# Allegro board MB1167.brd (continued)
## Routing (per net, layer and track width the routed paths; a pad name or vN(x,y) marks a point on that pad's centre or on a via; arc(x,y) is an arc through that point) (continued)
VBUS_FS1: length 209.4
  TOP w0.203: v1(9.27,101.47) 9.27,100.71 8.68,100.12 D5.B3
  TOP w0.381: v1(6.73,97.03) 5.36,98.4 CN13.1
  TOP w0.508: v1(111.89,124.26) 112.88,124.26 114.2,122.94 CN6.54 ; v1(6.73,97.03) 6.73,97 7.24,96.49 C48.1 8.31,93.29 U11.1 ; v1(9.27,101.47) 10.16,102.36 10.16,102.87 v1(10.67,103.38) R108.1 ; D9.1 v1(25.91,81.03)
  L4_SIG w0.508: v1(10.67,103.38) 11.05,103.76 19.68,103.76 22.35,101.09 24.64,101.09 26.42,99.31 32.79,99.31 36.96,103.48 36.96,105.41 43.69,112.14 43.69,116.33 46.37,119.01 46.44,119.01 48.59,121.16 58.8,121.16 60.69,119.27 95.52,119.27 97.66,121.41 106.43,121.41 108.97,123.95 108.97,126.11 107.95,127.13 107.95,127.89 v1(108.08,128.02) 110.62,128.02 111.89,126.75 v1(111.89,124.26) ; JP13.3 3.18,74.17 3.18,76.35 5.16,78.33 5.16,81.48 6.1,82.42 6.1,94.74 6.73,95.38 v1(6.73,97.03) 6.73,97.69 6.02,98.4 6.02,100.51 6.99,101.47 v1(9.27,101.47)
  BOTTOM w0.508: JP13.3 5.84,71.5 8.94,71.5 9.4,71.96 21.03,71.96 25.91,76.83 v1(25.91,81.03) ; v1(108.08,128.02) R261.2
VBUS_FS2: length 124.4
  TOP w0.254: v1(9.83,87.76) 9.83,86.79 8.81,85.77 D6.B3
  TOP w0.381: 5.36,84.04 CN14.1
  TOP w0.508: 5.36,84.04 5.87,84.04 7.37,82.55 R138.1 7.24,81.15 v1(6.1,81.15) ; SB13.1 v1(15.88,114.05) ; v1(39.37,129.29) 38.73,128.65 38.73,126.24 36.83,124.33 v1(29.84,124.33) ; D10.1 26.82,78.05 v1(26.75,77.98)
  L4_SIG w0.508: v1(6.1,81.15) 7.24,82.3 7.24,83.95 8,84.71 8,85.09 9.83,86.92 v1(9.83,87.76)
  BOTTOM w0.508: v1(6.1,81.15) 2.67,77.72 2.67,72.14 JP13.5 5.72,69.09 8.76,69.09 10.24,70.56 20.88,70.56 26.75,76.43 v1(26.75,77.98) ; v1(9.83,87.76) 9.91,87.83 9.91,106.81 10.67,107.57 11.81,107.57 14.73,110.49 14.73,112.9 v1(15.88,114.05) 15.88,116.89 17.48,118.49 20.95,118.49 23.62,121.16 23.62,122.68 25.27,124.33 v1(29.84,124.33) ; v1(39.37,129.29) R259.1
VBUS_HS: length 77.2
  TOP w0.203: v1(7.37,115.75) 7.75,116.13 D3.A1
  TOP w0.381: CN8.1 6.96,111.86 L2.2
  TOP w0.508: L2.2 v1(7.37,113.18) ; D8.1 v1(25.53,83.06)
  BOTTOM w0.508: v1(25.53,83.06) 25.4,83.06 25.15,82.8 25.15,77.34 21.84,74.04 5.84,74.04 JP13.1 4.57,77.98 7.16,80.56 7.16,82.63 5.97,83.82 5.97,100.58 7.37,101.98 v1(7.37,113.18) v1(7.37,115.75)
VDD_MCU: length 47.4
  TOP w0.381: U4.F5 v5(80.41,140.09) ; U4.E9 v5(81.21,136.89) U4.E8 ; v5(79.61,134.49) U4.G11 ; U4.F4 v5(80.41,140.89) ; v5(81.21,135.29) U4.E10 ; U4.K11 v5(76.41,134.49) ; v5(79.61,140.09) U4.G5 ; U4.F11 v5(80.41,134.49) ; U4.L8 v5(76.41,136.89) ; U4.E7 v5(80.41,138.49) ; U4.J5 v5(77.22,139.29) ; U4.H5 v5(78.01,139.29) ; U4.J11 v5(77.21,134.49) ; U4.H11 v5(78.01,134.49) ; U4.K5 v5(76.41,140.09) ; v5(75.61,138.49) U4.L7 ; U4.L10 v5(75.61,135.29) ; U4.L9 v5(75.61,136.09)
  TOP w0.508: C28.2 60.33,130.81 v1(60.2,130.68) ; C26.2 89.1,133.86 v1(88.77,134.19)
  BOTTOM w0.381: C122.1 81.92,137.59 v5(81.21,136.89) ; v5(75.61,138.49) 75.31,138.19 C125.1 ; v5(81.28,143.38) 81.66,143.76 C108.1 ; v5(78.01,139.29) 78.17,139.45 C118.1 ; C129.1 75.79,136.27 v5(75.61,136.09) ; v3(85.95,138.29) 85.83,138.18 85.72,138.18 85.34,137.79 C121.1 ; C132.1 72.64,135.38 72.14,134.87 v5(72.01,134.87) ; v3(77.93,145.01) 77.93,144.88 77.9,144.86 77.9,144.58 78.02,144.47 78.02,144.23 C109.1 ; v1(86.94,149.56) 86.49,149.1 C104.2 ; C131.1 78.74,135.36 v5(79.61,134.49) ; v5(85.72,140.84) 85.43,140.54 85.05,140.54 C116.1 ; C126.1 72.64,137.8 v5(72.06,138.38) 72.62,138.94 C117.1 ; C130.1 85.27,136.14 85.67,135.74 86.2,135.74 v5(86.28,135.66) ; C128.1 80.77,135.73 v5(81.21,135.29) ; v5(78.01,134.49) 78.26,134.24 C133.1 ; C123.1 80.77,138.12 v5(80.41,138.49) ; v5(79.61,140.09) 79.11,140.59 C114.1 ; v5(76.41,136.89) 76.45,136.93 C124.1
  BOTTOM w0.508: JP2.2 61.09,150.57 ; JP2.2 62.05,149.61 ; JP2.2 60.12,149.61 ; JP2.2 61.09,148.64 ; 61.09,146.3 61.09,147.27 ; 61.09,146.3 61.09,145.34 ; 61.09,146.3 60.25,146.3 ; 61.09,146.3 61.93,146.3 ; 61.09,142.67 61.09,143.64 ; 61.09,143.64 60.25,143.64 ; 61.09,143.64 61.93,143.64 ; 61.09,143.64 61.09,144.6 ; C115.1 59.94,141.58 ; C115.1 59.94,140.61 ; C115.1 60.43,141.1 ; 61.2,141.1 L7.1 ; L7.1 61.85,140.49 ; L7.1 61.85,141.71 ; C127.2 v1(59.94,137.41)
  vias: v1(60.2,139.95) v1(60.2,139.32) v1(60.96,139.95) v1(60.96,139.32) v1(61.72,139.95) v1(61.72,139.32)
VDDA: length 15.6
  TOP w0.381: U4.R1 72.26,142.89 72.14,143.01 v5(72.14,143.05)
  TOP w0.508: v3(68.07,143.64) 67.06,143.64 R33.1
  BOTTOM w0.381: C113.2 72.52,142.67 v5(72.14,143.05)
  BOTTOM w0.508: L7.2 TP9.1 C111.1 v3(68.07,143.64) 68.71,143.64 69.29,143.05 v5(72.14,143.05)
A0: length 133.9
  TOP w0.102: U13.G8 91.83,76.34 v5(91.44,75.95) ; 78.84,107.95 77.47,106.58 77.47,105.81 U9.E2 ; v5(69.74,77.85) 69.74,78.09 69.22,78.61 U14.A3
  TOP w0.127: 78.84,107.95 78.84,108.03 v4(78.89,108.08) ; CN11.14 v3(103.38,109.78)
  L4_SIG w0.102: v5(69.74,77.85) 69.74,77.84 70.21,77.37 71.32,77.37 71.42,77.47 71.7,77.47 71.9,77.27 72.11,77.27 72.31,77.47 72.51,77.47 72.72,77.27 72.92,77.27 73.12,77.47 73.33,77.47 73.53,77.27 73.73,77.27 73.94,77.47 74.14,77.47 74.34,77.27 74.55,77.27 74.75,77.47 74.95,77.47 75.16,77.27 75.36,77.27 75.56,77.47 75.77,77.47 75.97,77.27 76.17,77.27 76.38,77.47 76.58,77.47 76.78,77.27 76.98,77.27 77.19,77.47 77.39,77.47 77.59,77.27 77.8,77.27 78,77.47 78.2,77.47 78.41,77.27 78.61,77.27 78.81,77.47 79.21,77.47 v1(79.29,77.39) 79.57,77.11 83.59,77.11 84.28,77.81 89.83,77.81 91.44,76.2 v5(91.44,75.95) ; v3(103.38,109.78) 102.9,109.3 101.35,109.3 98.48,106.43 80.17,106.43 78.89,107.71 v4(78.89,108.08)
  BOTTOM w0.127: v1(79.29,77.39) 79.29,78.5 79.5,78.71 79.5,79.6 80.53,80.63 80.53,94.39 80.8,94.65 80.8,97.64 82.8,99.64 82.8,99.69 82.82,99.7 82.82,100.06 81.92,100.97 80.52,100.97 79.88,101.6 79.88,104.14 78.89,105.13 v4(78.89,108.08) ; R242.2 91.02,142.24 91.52,141.74 91.53,141.74 93.98,139.29 93.98,132.59 93.34,131.95 93.34,117.6 101.73,109.22 102.82,109.22 v3(103.38,109.78)
A1: length 133.4
  TOP w0.102: 79.88,107.95 78.51,106.58 78.51,105.77 U9.D2 ; U14.A4 69.2,77.86 v5(69.2,77.85) ; U13.G9 91.44,75.12 v5(91.44,75.06)
  TOP w0.127: 79.88,107.95 79.93,108 79.93,108.31 v4(80.26,108.64) ; CN11.12 v3(103.38,111.05)
  L4_SIG w0.102: v4(80.26,108.64) 80.26,108.46 81.53,107.19 97.89,107.19 101.22,110.52 102.84,110.52 v3(103.38,111.05) ; v5(91.44,75.06) 91.01,75.48 91.01,76.09 89.6,77.5 84.49,77.5 83.77,76.78 80.49,76.78 v1(80.39,76.68) 80.29,76.68 80.26,76.71 79.5,76.71 79.25,76.96 69.96,76.96 69.2,77.72 v5(69.2,77.85)
  BOTTOM w0.127: v1(80.39,76.68) 80.39,77.34 81.41,78.36 81.41,79.35 82.36,80.3 82.36,82.71 82.98,83.33 82.98,86.49 85.09,88.6 85.09,102.11 83.03,104.17 83.03,105.66 80.26,108.43 v4(80.26,108.64) ; R240.2 91.44,142.75 92.04,142.75 93.22,141.57 93.22,141.13 94.74,139.61 94.74,132.21 94.11,131.57 94.11,118.19 101.83,110.46 102.9,110.46 103.38,110.95 v3(103.38,111.05)
A2: length 130.1
  TOP w0.102: v5(70.89,77.72) 70.87,77.72 70.25,77.11 U14.A5 ; 81.33,107.95 81.33,107.62 80.47,106.76 80.47,105.93 U9.C2 ; v5(91.44,77.72) 92.08,77.72 U13.F7
  TOP w0.127: v4(81.33,108.53) 81.33,107.95 ; CN11.8 v3(103.38,113.59)
  L4_SIG w0.102: v5(70.89,77.72) 70.97,77.72 71.07,77.82 79.66,77.82 79.93,77.55 v1(81.41,77.55) 83.49,77.55 84.06,78.11 84.45,78.11 84.46,78.11 91.06,78.11 v5(91.44,77.72) ; v4(81.33,108.53) 81.92,107.95 96.95,107.95 101.98,112.98 102.77,112.98 v3(103.38,113.59)
  BOTTOM w0.127: v3(103.38,113.59) 102.77,112.98 100.69,112.98 94.87,118.8 94.87,131.06 95.5,131.7 95.5,139.92 93.98,141.45 93.98,141.99 92.08,143.89 91.57,143.89 R239.2 ; v4(81.33,108.53) 81.33,108.51 83.92,105.92 83.92,104.36 85.85,102.43 85.85,88.24 83.74,86.13 83.74,82.98 83.44,82.68 83.44,80.14 83.12,79.82 82.42,79.82 81.79,79.19 81.79,77.98 81.41,77.6 v1(81.41,77.55)
A3: length 127.3
  TOP w0.102: U14.B3 v5(68.29,78.98) ; v5(92.2,79.88) U13.F3 ; U9.A2 81.94,105.37 82.45,105.88 82.45,107.95
  TOP w0.127: v4(82.25,108.66) 82.45,108.46 82.45,107.95 ; v3(101.98,114.68) 101.8,114.86 CN11.5
  L4_SIG w0.102: v3(101.98,114.68) 101.85,114.68 96.77,109.6 83.97,109.6 83.41,109.04 82.6,109.04 82.25,108.69 v4(82.25,108.66) ; v5(92.2,79.88) 93.22,79.88 93.34,80.01 93.34,80.21 93.22,80.34 91.9,80.34 91.77,80.21 91.77,79.78 91.67,79.68 91.52,79.68 91.41,79.78 91.41,80.31 91.31,80.42 91.16,80.42 91.06,80.31 91.06,79.81 90.93,79.68 83.24,79.68 v1(82.93,79.38) 82.61,79.69 70.32,79.69 69.75,79.12 68.43,79.12 v5(68.29,78.98)
  BOTTOM w0.127: v1(82.93,79.38) 83.69,79.38 83.95,79.63 83.95,82.55 84.12,82.73 84.12,85.95 86.23,88.06 86.23,102.59 84.23,104.59 84.23,106.37 82.25,108.35 v4(82.25,108.66) ; v3(101.98,114.68) 101.12,114.68 97.54,118.26 97.54,130.53 96.9,131.17 96.9,139.7 95,141.6 95,142.24 92.08,145.16 91.57,145.16 R236.2
A4: length 133.3
  TOP w0.102: 81.79,107.95 81.79,106.93 81.43,106.58 81.43,105.89 U9.B2 ; v5(92.24,81.53) 92.2,81.57 92.2,81.6 U13.G1 ; U14.B4 68.3,77.47 69.98,77.47 70.23,77.72 70.23,79.01 70.35,79.13 v5(70.35,79.17)
  TOP w0.127: v3(101.93,115.7) 101.6,115.7 101.17,116.13 CN11.3 ; 81.79,107.95 81.79,109.09 82.25,109.55 v4(82.25,109.58)
  L4_SIG w0.102: v5(70.35,79.17) 70.39,79.17 70.61,79.39 82.07,79.39 v1(82.36,79.1) 82.44,79.1 82.61,78.92 83.11,78.92 83.54,79.35 93.73,79.35 93.85,79.48 93.85,81.41 93.73,81.53 v5(92.24,81.53) ; v3(101.93,115.7) 101.6,115.7 96.39,110.49 83.49,110.49 82.58,109.58 v4(82.25,109.58)
  BOTTOM w0.127: R233.2 91.31,147.19 95.9,142.61 96.22,142.61 97.66,141.16 97.66,131.83 99.95,129.54 99.95,117.68 v3(101.93,115.7) ; v4(82.25,109.58) 82.68,109.14 82.68,108.46 82.96,108.18 85.17,105.97 85.17,104.19 86.74,102.62 86.74,88.01 84.51,85.78 84.51,82.57 84.33,82.39 84.33,79.43 83.64,78.74 82.72,78.74 v1(82.36,79.1)
A5: length 132
  TOP w0.102: 79.5,107.95 78.31,106.76 78.31,104.97 U9.D3 ; U13.G2 92.2,80.8 92.2,80.77 v5(92.22,80.75) ; U14.C3 v5(67.54,78.98)
  TOP w0.127: v4(80.39,109.4) 80.19,109.4 79.5,108.71 79.5,107.95 ; CN11.1 101.07,117.4 v3(101.85,118.19)
  L4_SIG w0.102: v4(80.39,109.4) 80.44,109.4 82.04,111 94.67,111 v3(101.85,118.19) ; v5(67.54,78.98) 68.01,79.45 69.75,79.45 70.31,80.01 82.65,80.01 v1(82.91,80.26) 84.18,80.26 84.56,79.88 90.65,79.88 90.78,80.01 90.78,80.14 90.65,80.26 90.37,80.26 90.25,80.39 90.25,80.52 90.37,80.64 90.7,80.64 90.83,80.77 90.83,81.03 90.95,81.15 91.13,81.15 91.26,81.03 91.26,80.82 91.36,80.72 91.56,80.72 91.66,80.82 91.66,81.05 91.76,81.15 93.38,81.15 93.5,81.03 93.5,80.87 93.38,80.75 v5(92.22,80.75)
  BOTTOM w0.127: v4(80.39,109.4) 80.87,108.92 80.87,108.36 81.28,107.95 83.54,105.69 83.54,104.2 85.47,102.27 85.47,88.42 83.36,86.31 83.36,83.17 82.91,82.72 v1(82.91,80.26) ; v3(101.85,118.19) 100.33,123.83 100.33,129.76 98.04,134.42 98.04,141.99 95.87,144.16 95.11,144.16 R232.2
A6: length 127.5
  TOP w0.102: U14.C4 v5(67.54,77.48) ; U9.C3 v4(80.41,104.87) ; v5(91.44,78.99) 91.44,79.6 91.64,79.8 91.64,80.12 U13.G3
  TOP w0.127: CN10.5 52.78,114.86 v3(53.47,114.17)
  L4_SIG w0.102: v5(67.54,77.48) 68.26,78.21 79.7,78.21 79.93,77.98 v1(80.33,77.98) 83.49,77.98 83.93,78.42 84.39,78.42 84.45,78.36 90.81,78.36 v5(91.44,78.99) ; v3(53.47,114.17) 53.98,114.17 54.48,113.67 69.72,113.67 78.52,104.87 v4(80.41,104.87)
  BOTTOM w0.127: R255.2 66.04,132.84 65.41,132.21 63.37,132.21 62.87,131.7 62.87,121.11 56.57,114.81 54.1,114.81 v3(53.47,114.17) ; v1(80.33,77.98) 80.33,79.35 81.6,80.62 81.6,83.25 82.22,83.87 82.22,91.08 82.35,91.21 84.2,91.21 84.33,91.34 84.33,91.59 84.2,91.72 82.35,91.72 82.22,91.85 82.22,92.1 82.35,92.23 84.2,92.23 84.33,92.35 84.33,92.61 84.2,92.74 82.35,92.74 82.22,92.86 82.22,93.12 82.35,93.24 84.2,93.24 84.33,93.37 84.33,101.88 83.95,102.26 83.95,102.49 83.31,103.12 82.17,103.12 81.74,103.55 81.74,103.73 81.8,103.79 81.8,103.97 81.62,104.15 81.44,104.15 81.38,104.09 81.2,104.09 80.42,104.87 v4(80.41,104.87)
A7: length 131.6
  TOP w0.102: U13.H1 91.44,81.56 91.44,79.88 90.68,79.12 90.45,79.12 v5(90.32,78.99) ; U14.D4 v5(66.79,77.48) ; U9.A3 v4(81.45,104.83)
  TOP w0.127: v3(53.47,115.44) 53.34,115.44 52.65,116.13 CN10.3
  L4_SIG w0.102: v3(53.47,115.44) 54.13,114.78 70.64,114.78 79.88,105.54 80.74,105.54 v4(81.45,104.83) ; v5(66.79,77.48) 67.72,78.41 69.49,78.41 69.6,78.51 80.84,78.51 v1(80.87,78.49) 81.07,78.28 83.36,78.28 83.82,78.74 84.45,78.74 84.56,78.64 90.27,78.64 90.32,78.69 v5(90.32,78.99)
  BOTTOM w0.127: v3(53.47,115.44) 54.34,115.44 54.69,115.8 56.34,115.8 62.08,121.54 62.08,132.44 63.12,133.48 65.15,133.48 65.79,134.11 R253.2 ; v1(80.87,78.49) 80.87,79.35 81.98,80.46 81.98,82.87 82.6,83.49 82.6,87.6 82.73,87.72 83.67,87.72 83.79,87.85 83.79,88.1 83.67,88.23 82.73,88.23 82.6,88.36 82.6,88.65 82.73,88.77 84.58,88.77 84.71,88.9 84.71,89.15 84.58,89.28 82.75,89.28 82.63,89.41 82.63,89.66 82.75,89.79 84.58,89.79 84.71,89.92 84.71,90.17 84.58,90.3 82.75,90.3 82.63,90.42 82.63,90.68 82.75,90.81 84.58,90.81 84.71,90.93 84.71,101.95 84.45,102.21 84.45,102.36 83.19,103.63 82.91,103.63 81.71,104.83 v4(81.45,104.83)
A8: length 135.3
  TOP w0.102: v4(81.41,101.88) 81.41,101.87 U9.B6 ; v5(90.66,81.54) U13.H2 ; U14.H2 v5(63.04,79.73)
  TOP w0.127: v3(54.9,115.3) 54.91,115.32 54.99,115.32 55.8,116.13 CN10.4
  L4_SIG w0.102: v5(63.04,79.73) 63.04,80.26 63.37,80.6 63.37,83.31 64.9,84.84 v1(81.37,84.84) 81.37,85.88 81.5,86 81.74,86 81.86,85.88 81.86,85.5 81.99,85.37 82.22,85.37 82.32,85.47 82.32,85.89 82.44,86 82.61,86 82.73,85.89 82.73,85.47 82.83,85.37 83.03,85.37 83.13,85.47 83.13,85.89 83.25,86 83.42,86 83.54,85.89 83.54,85.47 83.64,85.37 83.85,85.37 83.95,85.47 83.95,85.89 84.07,86 84.23,86 84.35,85.89 84.35,85.47 84.45,85.37 84.66,85.37 84.76,85.47 84.76,85.89 84.88,86 85.05,86 85.17,85.89 85.17,85.47 85.27,85.37 85.47,85.37 85.57,85.47 85.57,85.89 85.69,86 85.86,86 85.98,85.89 85.98,85.47 86.08,85.37 86.33,85.37 86.46,85.5 86.46,85.88 86.59,86 86.74,86 86.87,85.88 86.87,84.86 87,84.73 87.86,84.73 87.96,84.84 87.96,85.29 88.06,85.39 88.27,85.39 88.37,85.29 88.37,84.84 88.47,84.73 89.87,84.73 90.27,84.33 90.27,82.22 90.66,81.83 v5(90.66,81.54) ; v4(81.41,101.88) 81.92,102.39 81.92,104.92 81.1,105.74 80.11,105.74 70.55,115.3 v3(54.9,115.3)
  BOTTOM w0.127: v1(81.37,84.84) 81.37,94.09 81.56,94.28 81.56,95.96 81.69,96.09 83.44,96.09 83.57,96.22 83.57,96.47 83.44,96.6 81.84,96.6 81.71,96.72 81.71,96.98 81.84,97.1 83.44,97.1 83.57,97.23 83.57,97.49 83.44,97.61 82.42,97.61 82.3,97.74 82.3,97.99 82.42,98.12 83.44,98.12 83.57,98.25 83.57,100.2 82.18,101.59 82.18,102.02 81.33,102.87 80.85,102.87 80.72,103 80.72,103.45 80.59,103.58 80.34,103.58 80.21,103.45 80.21,102.46 80.34,102.34 81.28,102.34 81.41,102.21 v4(81.41,101.88) ; v3(54.9,115.3) 54.91,115.32 56.41,115.32 62.46,121.36 62.46,131.93 63.37,132.84 R256.2
A9: length 134.9
  TOP w0.102: U14.H3 v5(63.04,78.98) ; v4(83.31,101.21) 82.07,101.21 U9.A6 ; v5(89.86,80.74) U13.J3
  TOP w0.127: CN10.18 v3(54.86,107.24)
  L4_SIG w0.102: v5(89.86,80.74) 89.86,80.99 90.22,81.36 90.22,81.86 89.92,82.17 89.92,84.25 89.79,84.38 86.56,84.38 86.46,84.48 86.46,84.94 86.36,85.04 86.15,85.04 86.05,84.94 86.05,84.4 85.93,84.28 85.76,84.28 85.64,84.4 85.64,84.95 85.52,85.06 85.36,85.06 85.24,84.95 85.24,84.45 85.12,84.33 84.95,84.33 84.83,84.45 84.83,84.95 84.71,85.06 84.54,85.06 84.42,84.95 84.42,84.19 84.31,84.07 84.14,84.07 84.02,84.19 84.02,84.95 83.9,85.06 83.73,85.06 83.61,84.95 83.61,84.19 83.49,84.07 83.32,84.07 83.21,84.19 83.21,84.95 83.09,85.06 82.92,85.06 82.8,84.95 82.8,84.2 82.67,84.07 82.45,84.07 82.32,84.2 82.32,84.94 82.19,85.06 81.97,85.06 81.84,84.94 81.84,84.33 81.71,84.2 v1(81.37,84.2) 64.9,84.2 63.75,83.06 63.75,80.58 63.43,80.26 63.43,79.38 v5(63.04,78.98) ; v4(83.31,101.21) 82.54,101.21 82.17,100.84 79.54,100.84 78.9,101.48 76.54,101.48 76.51,101.51 73.04,101.51 72.69,101.85 71.78,101.85 71.25,101.32 70.84,101.32 64.92,107.24 v3(54.86,107.24)
  BOTTOM w0.127: R266.2 68.07,125.09 68.07,117.47 57.91,107.31 54.94,107.31 v3(54.86,107.24) ; v1(81.37,84.2) 81.37,84.21 81.84,84.68 81.84,93.52 81.97,93.65 83.82,93.65 83.95,93.78 83.95,94.03 83.82,94.16 82.07,94.16 81.94,94.28 81.94,94.54 82.07,94.67 83.82,94.67 83.95,94.79 83.95,95.05 83.82,95.17 82.07,95.17 81.94,95.3 81.94,95.55 82.07,95.68 83.82,95.68 83.95,95.81 83.95,101.73 83.82,101.85 82.98,101.85 82.85,101.73 82.85,101.33 82.98,101.21 v4(83.31,101.21)
A10: length 133.1
  TOP w0.102: v5(91.48,76.76) U13.G7 ; U9.C6 79.93,101.37 v4(80.41,101.85) ; U14.H4 v5(63.04,77.48)
  TOP w0.127: CN10.6 55.42,114.86 v3(54.74,114.17)
  L4_SIG w0.102: v3(54.74,114.17) 70.74,114.17 79.65,105.26 80.57,105.26 80.8,105.03 80.8,102.25 v4(80.41,101.85) ; v5(91.48,76.76) 91.8,76.45 91.8,74.85 90.18,73.24 89.32,73.24 88.75,72.67 88.58,72.67 88.09,73.16 87.94,73.16 87.8,73.02 87.8,72.87 88.38,72.29 88.38,72.13 88.26,72.01 88.09,72.01 87.51,72.59 87.37,72.59 87.23,72.44 87.23,72.3 87.76,71.77 87.76,71.67 87.34,71.25 v1(79.38,71.25) 67.23,71.25 62.61,75.87 62.61,77.05 v5(63.04,77.48)
  BOTTOM w0.127: v1(79.38,71.25) 79.88,71.75 79.88,79.44 80.91,80.47 80.91,94.22 81.18,94.49 81.18,97.43 83.19,99.44 83.19,100.15 81.99,101.35 80.92,101.35 v4(80.41,101.85) ; v3(54.74,114.17) 54.86,114.3 56.74,114.3 63.25,120.8 63.25,131.19 R258.2
A11: length 134.5
  TOP w0.102: U9.D6 78.36,101.92 v4(78.36,103.89) ; U14.H5 v5(63.04,76.73) ; v5(90.66,75.14) U13.H9
  TOP w0.127: CN10.7 52.91,113.59 v3(53.34,113.16)
  L4_SIG w0.102: v4(78.36,103.89) 78.36,104.52 71.25,111.63 62.68,111.63 62.57,111.73 62.57,111.91 62.47,112.01 62.27,112.01 62.17,111.91 62.17,111.73 62.07,111.63 61.86,111.63 61.76,111.73 61.76,111.91 61.66,112.01 61.46,112.01 61.36,111.91 61.36,111.73 61.25,111.63 61.05,111.63 60.95,111.73 60.95,111.91 60.85,112.01 60.64,112.01 60.54,111.91 60.54,111.73 60.44,111.63 60.24,111.63 60.14,111.73 60.14,111.91 60.03,112.01 59.83,112.01 59.73,111.91 59.73,111.73 59.63,111.63 59.43,111.63 59.32,111.73 59.32,111.91 59.22,112.01 59.02,112.01 58.92,111.91 58.92,111.73 58.82,111.63 58.61,111.63 58.51,111.73 58.51,111.91 58.41,112.01 58.21,112.01 58.1,111.91 58.1,111.73 58,111.63 57.8,111.63 57.7,111.73 57.7,111.91 57.6,112.01 57.39,112.01 57.29,111.91 57.29,111.73 57.19,111.63 56.99,111.63 56.89,111.73 56.89,111.91 56.78,112.01 56.58,112.01 56.48,111.91 56.48,111.73 56.38,111.63 56.17,111.63 56.07,111.73 56.07,111.91 55.97,112.01 55.77,112.01 55.67,111.91 55.67,111.73 55.56,111.63 54.48,111.63 53.98,112.14 53.98,112.52 v3(53.34,113.16) ; v5(90.66,75.14) 90.66,74.17 90.18,73.7 89.15,73.7 89.05,73.8 89.05,74.68 88.93,74.8 88.77,74.8 88.65,74.68 88.65,73.8 88.54,73.7 88.02,73.7 86.71,72.38 86.71,72.24 86.93,72.02 86.93,71.87 86.79,71.73 86.65,71.73 86.42,71.95 86.28,71.95 86.08,71.75 v1(78.61,71.75) 67.31,71.75 63.4,75.67 63.4,76.38 v5(63.04,76.73)
  BOTTOM w0.127: v1(78.61,71.75) 79.5,72.64 79.5,76.55 78.49,77.57 78.49,79.66 79.76,80.93 79.76,94.82 80.01,95.07 80.01,98.68 78.99,99.69 78.99,100.84 78.87,100.97 78.87,103.38 v4(78.36,103.89) ; v3(53.34,113.16) 53.85,113.67 56.69,113.67 63.65,120.62 63.65,128.93 R257.2
A12: length 116.3
  TOP w0.102: v5(63.79,78.98) U14.G3 ; U9.B7 v4(81.41,99.87)
  TOP w0.127: CN10.33 53.29,97.08 v3(53.42,97.21)
  L4_SIG w0.102: v4(81.41,99.87) 81.41,99.87 81.41,98.68 79.78,97.05 75.41,97.05 75.08,97.38 55.68,97.38 55.02,96.72 54.28,96.72 53.8,97.21 v3(53.42,97.21)
  BOTTOM w0.127: v5(63.79,78.98) 64.77,79.96 68.72,79.96 69.11,80.35 69.11,82.22 66.42,84.91 66.42,100.33 70.99,104.9 74.68,104.9 74.93,105.16 78.52,105.16 79.63,104.05 79.63,101.47 81.23,99.87 v4(81.41,99.87) ; v3(53.42,97.21) 54,97.79 56.26,97.79 73.66,115.19 73.66,122.17 R272.2
A13: length 120.6
  TOP w0.102: v5(63.79,77.48) U14.G4 ; U9.A7 v4(82.41,99.87)
  TOP w0.127: v3(54.86,97.28) 55.07,97.08 CN10.34
  L4_SIG w0.102: v3(54.86,97.28) 55.02,97.28 55.45,97.71 75.26,97.71 75.59,97.38 79.48,97.38 80.9,98.81 80.9,99.92 81.31,100.33 81.95,100.33 v4(82.41,99.87)
  BOTTOM w0.127: R262.2 74.68,125.09 74.68,123.96 74.42,123.7 74.42,121.79 74.04,121.41 74.04,114.81 56.44,97.21 54.94,97.21 v3(54.86,97.28) ; v5(63.79,77.48) 64.29,77.98 64.72,77.98 66.12,79.38 69.22,79.38 70,80.16 70,83.21 67.18,86.03 67.18,99.82 71.37,104.01 74.99,104.01 75.5,104.52 78.49,104.52 79.12,103.89 79.12,101.09 79.88,100.33 79.88,99.69 80.16,99.42 81.96,99.42 v4(82.41,99.87)
A14: length 130.1
  TOP w0.102: U13.J7 89.79,77.61 v5(89.79,78.99) ; U14.F3 v5(64.54,78.98) ; U9.C7 79.49,99.95 v4(79.48,99.95)
  TOP w0.127: CN10.28 v3(54.86,100.89)
  L4_SIG w0.102: v5(89.79,78.99) 84.44,78.99 84.39,79.04 83.7,79.04 83.24,78.59 82.07,78.59 81.94,78.71 81.94,78.96 81.83,79.07 81.67,79.07 81.56,78.96 81.56,78.82 81.43,78.69 81.28,78.69 81.15,78.82 81.15,78.94 81.03,79.07 80.5,79.07 80.4,78.97 80.4,78.92 80.3,78.82 80.1,78.82 80,78.92 80,78.97 79.89,79.07 79.09,79.07 v1(78.98,78.96) 70.84,78.96 70.7,78.82 69.35,78.82 69.15,78.61 65.02,78.61 64.65,78.98 v5(64.54,78.98) ; v3(54.86,100.89) 55.47,100.89 55.57,100.79 55.57,100.05 55.68,99.95 55.88,99.95 55.98,100.05 55.98,100.79 56.08,100.89 56.29,100.89 56.39,100.79 56.39,100.05 56.49,99.95 56.69,99.95 56.79,100.05 56.79,100.79 56.89,100.89 57.1,100.89 57.2,100.79 57.2,100.05 57.3,99.95 57.5,99.95 57.61,100.05 57.61,100.79 57.71,100.89 57.91,100.89 58.01,100.79 58.01,100.05 58.11,99.95 58.32,99.95 58.42,100.05 58.42,100.79 58.52,100.89 58.72,100.89 58.83,100.79 58.83,100.05 58.93,99.95 59.13,99.95 59.23,100.05 59.23,100.79 59.33,100.89 59.54,100.89 59.64,100.79 59.64,100.05 59.74,99.95 59.94,99.95 60.04,100.05 60.04,100.79 60.15,100.89 60.35,100.89 60.45,100.79 60.45,100.05 60.55,99.95 60.76,99.95 60.86,100.05 60.86,100.79 60.96,100.89 61.16,100.89 61.26,100.79 61.26,100.05 61.37,99.95 61.57,99.95 61.67,100.05 61.67,100.79 61.77,100.89 61.97,100.89 62.08,100.79 62.08,100.05 62.18,99.95 62.38,99.95 62.48,100.05 62.48,100.79 62.58,100.89 62.79,100.89 62.89,100.79 62.89,100.05 62.99,99.95 63.19,99.95 63.3,100.05 63.3,100.79 63.4,100.89 63.6,100.89 63.7,100.79 63.7,100.05 63.8,99.95 64.01,99.95 64.11,100.05 64.11,100.79 64.21,100.89 64.41,100.89 64.51,100.79 64.51,100.05 64.62,99.95 64.82,99.95 64.92,100.05 64.92,100.79 65.02,100.89 65.99,100.89 68.2,98.68 77.57,98.68 78.21,99.31 78.84,99.31 v4(79.48,99.95)
  BOTTOM w0.127: R273.2 72.39,120.21 72.49,120.11 72.49,115.8 57.66,100.97 54.94,100.97 v3(54.86,100.89) ; v4(79.48,99.95) 79.48,99.72 80.39,98.81 80.39,94.79 80.14,94.54 80.14,80.77 78.98,79.62 v1(78.98,78.96)
A15: length 133.4
  TOP w0.102: U9.D7 78.91,100.37 78.37,99.83 v4(78.36,99.83) ; U14.F4 v5(64.54,77.48) ; v5(90.66,75.94) U13.H8
  TOP w0.127: CN10.25 v3(53.42,102.16)
  L4_SIG w0.102: v4(78.36,99.83) 77.58,99.06 68.4,99.06 65.99,101.47 65.5,101.47 65.4,101.57 65.4,102.16 65.3,102.26 65.1,102.26 64.99,102.16 64.99,101.57 64.89,101.47 64.69,101.47 64.59,101.57 64.59,102.16 64.49,102.26 64.28,102.26 64.18,102.16 64.18,101.57 64.08,101.47 63.88,101.47 63.78,101.57 63.78,102.16 63.67,102.26 63.47,102.26 63.37,102.16 63.37,101.57 63.27,101.47 63.06,101.47 62.96,101.57 62.96,102.16 62.86,102.26 62.66,102.26 62.56,102.16 62.56,101.57 62.45,101.47 62.25,101.47 62.15,101.57 62.15,102.16 62.05,102.26 61.84,102.26 61.74,102.16 61.74,101.57 61.64,101.47 61.44,101.47 61.34,101.57 61.34,102.16 61.24,102.26 61.03,102.26 60.93,102.16 60.93,101.57 60.83,101.47 60.63,101.47 60.52,101.57 60.52,102.16 60.42,102.26 60.22,102.26 60.12,102.16 60.12,101.57 60.02,101.47 59.81,101.47 59.71,101.57 59.71,102.16 59.61,102.26 59.41,102.26 59.3,102.16 59.3,101.57 59.2,101.47 59,101.47 58.9,101.57 58.9,102.16 58.8,102.26 58.59,102.26 58.49,102.16 58.49,101.57 58.39,101.47 58.19,101.47 58.09,101.57 58.09,102.16 57.98,102.26 57.78,102.26 57.68,102.16 57.68,101.57 57.58,101.47 57.37,101.47 57.27,101.57 57.27,102.16 57.17,102.26 56.97,102.26 56.87,102.16 56.87,101.57 56.76,101.47 56.56,101.47 56.46,101.57 56.46,102.16 56.36,102.26 56.16,102.26 56.05,102.16 56.05,101.57 55.95,101.47 54.1,101.47 v3(53.42,102.16) ; v5(64.54,77.48) 64.93,77.09 67.69,77.09 69.37,77.09 69.88,76.58 78.74,76.58 78.94,76.38 v1(78.99,76.38) 79.12,76.25 80.7,76.25 80.92,76.48 84.01,76.48 84.83,77.3 89.36,77.3 89.48,77.17 89.48,76.07 89.61,75.95 89.84,75.95 89.97,76.07 89.97,76.17 90.09,76.3 90.3,76.3 90.53,76.07 90.53,76.07 90.65,75.94 v5(90.66,75.94)
  BOTTOM w0.127: R264.2 71.88,125.09 71.88,124.49 71.5,124.11 71.5,120.9 71.12,120.52 71.12,116.15 57.84,102.87 54.13,102.87 v3(53.42,102.16) ; v4(78.36,99.83) 78.36,99.44 78.74,99.06 78.74,94.49 79.38,93.85 79.38,81.09 78.11,79.82 78.11,77.27 v1(78.99,76.38)
A16: length 114.2
  TOP w0.102: v4(77.42,99.83) 77.42,99.88 U9.E7 ; v5(65.29,77.48) U14.E4
  TOP w0.127: v3(53.39,104.65) 53.34,104.7 CN10.21
  L4_SIG w0.102: v4(77.42,99.83) 77.4,99.82 68.91,99.82 64.72,104.01 54.1,104.01 53.47,104.65 v3(53.39,104.65)
  BOTTOM w0.127: v5(65.29,77.48) 65.67,77.48 65.81,77.34 65.81,76.17 65.94,76.05 66.22,76.05 66.34,76.17 66.34,76.97 66.47,77.1 67.92,77.1 68.05,76.97 68.05,76.02 68.17,75.9 68.48,75.9 68.61,76.02 68.61,77.32 68.73,77.44 69.1,77.44 69.23,77.32 69.23,76.35 69.36,76.23 69.61,76.23 69.74,76.35 69.74,77.32 69.87,77.44 70.12,77.44 70.25,77.32 70.25,76 70.37,75.87 70.63,75.87 70.75,76 70.75,77.19 70.88,77.32 71.32,77.32 71.45,77.44 71.45,82.96 67.94,86.46 67.94,99.41 71.79,103.25 73.41,103.25 73.53,103.38 77.48,103.38 77.82,103.04 77.82,103.03 78.11,102.74 78.11,101.6 77.42,100.91 v4(77.42,99.83) ; v3(53.39,104.65) 53.39,104.67 54.13,105.41 57.99,105.41 69.6,117.02 69.6,124.21 R265.1
A17: length 114.8
  TOP w0.102: U9.B3 80.9,104.37 80.44,103.91 79.76,103.91 79.53,103.68 79.53,102.97 79.29,102.74 79.29,101.11 79.02,100.84 v4(78.46,100.84) ; v5(66.79,78.98) U14.D3
  TOP w0.127: CN10.23 v3(53.42,103.43)
  L4_SIG w0.102: v3(53.42,103.43) 54.1,102.74 65.38,102.74 68.68,99.44 77.68,99.44 77.97,99.73 77.97,100.34 v4(78.46,100.84)
  BOTTOM w0.127: R274.2 70.36,121.67 70.36,116.59 57.78,104.01 54,104.01 v3(53.42,103.43) ; v4(78.46,100.84) 78.61,100.99 78.61,103.07 78.2,103.48 78.19,103.48 77.85,103.82 77.85,104.14 77.71,104.28 75.7,104.28 75.06,103.63 71.63,103.63 67.56,99.57 67.56,86.21 70.38,83.39 70.38,83.03 70.51,82.91 70.92,82.91 71.04,82.78 71.04,82.58 70.92,82.45 70.51,82.45 70.38,82.32 70.38,82.04 70.51,81.92 70.84,81.92 70.97,81.79 70.97,81.53 70.84,81.41 70.51,81.41 70.38,81.28 70.38,81.03 70.51,80.9 70.84,80.9 70.97,80.77 70.97,80.52 70.84,80.39 70.51,80.39 70.38,80.26 70.38,80.01 70.51,79.88 70.84,79.88 70.97,79.76 70.97,78.23 70.84,78.11 70.07,78.11 69.94,78.23 69.94,79.04 69.82,79.17 69.56,79.17 69.44,79.04 69.44,78.38 69.31,78.26 69.05,78.26 68.93,78.38 68.93,78.49 68.8,78.61 68.55,78.61 68.42,78.49 68.42,78.05 68.29,77.93 68.04,77.93 67.91,78.05 67.91,78.49 67.78,78.61 67.53,78.61 67.4,78.49 67.4,78.05 67.28,77.93 66.57,77.93 66.45,78.05 66.45,78.85 66.57,78.98 v5(66.79,78.98)
A18: length 122.8
  TOP w0.102: U9.C4 79.91,102.91 79.53,102.53 79.53,101.07 79.76,100.84 80.14,100.84 80.39,100.58 v4(80.39,99.85) ; v5(62.23,78.74) 62.23,79.74 62.59,80.11 U14.H1
  TOP w0.127: CN10.31 v3(53.42,98.35)
  L4_SIG w0.102: v3(53.42,98.35) 53.98,97.79 55.02,97.79 55.45,98.22 79.57,98.22 80.39,99.05 v4(80.39,99.85)
  BOTTOM w0.127: v4(80.39,99.85) 80.39,100.33 79.38,101.35 79.38,103.98 78.56,104.79 75.2,104.79 74.84,104.43 71.16,104.43 66.8,100.08 66.8,85.14 69.62,82.32 69.62,80.32 68.98,79.68 65.94,79.68 64.62,78.36 62.61,78.36 v5(62.23,78.74) ; v3(53.42,98.35) 54.13,99.06 56.36,99.06 72.89,115.59 72.89,123.79 73.28,124.18 73.28,125.09 R263.2
A19: length 127.2
  TOP w0.102: v4(80.08,107.08) 79.53,106.53 79.53,104.14 79.29,103.9 79.29,103.21 78.91,102.83 U9.D5 ; v5(63.79,79.73) U14.G2
  TOP w0.127: CN11.13 v3(101.98,109.78) ; R37.2 v3(91.73,142.24) 92.22,142.24 92.35,142.11 R38.2
  L4_SIG w0.102: v3(101.98,109.78) 101.14,109.78 98.17,106.81 80.35,106.81 v4(80.08,107.08)
  BOTTOM w0.127: v3(91.73,142.24) 92.84,141.13 92.84,140.97 94.36,139.45 94.36,132.37 93.73,131.73 93.73,117.91 101.85,109.78 v3(101.98,109.78) ; v5(63.79,79.73) 63.65,79.87 63.65,84.78 63.78,84.9 65.02,84.9 65.15,85.03 65.15,85.29 65.02,85.41 63.86,85.41 63.73,85.54 63.73,85.79 63.86,85.92 65.33,85.92 65.46,86.05 65.46,86.3 65.33,86.43 63.86,86.43 63.73,86.56 63.73,86.81 63.86,86.94 65.33,86.94 65.46,87.06 65.46,87.32 65.33,87.44 63.86,87.44 63.73,87.57 63.73,87.83 63.86,87.95 65.33,87.95 65.46,88.08 65.46,88.33 65.33,88.46 63.91,88.46 63.78,88.59 63.78,88.84 63.91,88.97 65.33,88.97 65.46,89.1 65.46,89.35 65.33,89.48 63.96,89.48 63.83,89.6 63.83,89.86 63.96,89.98 65.33,89.98 65.46,90.11 65.46,100.51 73.53,108.58 78.99,108.58 79.5,108.08 79.5,107.65 v4(80.08,107.08)
A20: length 129
  TOP w0.102: U9.D4 78.91,103.83 79.3,104.22 79.3,106.98 80.26,107.95 80.39,107.95 ; U14.H6 v5(63.04,75.98)
  TOP w0.127: R36.2 v3(91.82,143.38) R35.2 ; CN11.11 v3(101.98,111.05) ; 80.39,107.95 80.87,108.43 80.87,109.07 v4(81.36,109.55)
  L4_SIG w0.102: v4(81.36,109.55) 80.85,109.04 80.85,108.38 81.66,107.57 97.54,107.57 101.02,111.05 v3(101.98,111.05)
  BOTTOM w0.127: v3(91.82,143.38) 91.95,143.38 93.6,141.73 93.6,141.29 95.12,139.77 95.12,131.95 94.49,131.32 94.49,118.52 101.96,111.05 v3(101.98,111.05) ; v4(81.36,109.55) 81.36,109.65 80.9,110.11 73.83,110.11 64.57,100.86 64.57,93.14 64.45,93.01 63.17,93.01 63.04,92.89 63.04,92.63 63.17,92.51 64.45,92.51 64.57,92.38 64.57,92.13 64.45,92 63.17,92 63.04,91.87 63.04,91.62 63.17,91.49 64.45,91.49 64.57,91.36 64.57,91.11 64.45,90.98 62.99,90.98 62.87,90.86 62.87,80.82 62.74,80.7 61.37,80.7 61.24,80.57 61.24,77.8 62.56,76.48 62.56,76.46 v5(63.04,75.98)
A21: length 74.9
  TOP w0.102: 83.57,107.95 83.57,103.89 82.67,102.99 81.75,102.99 81.74,103 81.08,103 81.07,102.99 80.53,102.99 U9.C5
  TOP w0.127: CN11.4 104.22,116.13 103.66,115.57 v3(103.5,115.57) ; v4(83.19,109.52) 83.19,109.22 83.57,108.84 83.57,107.95 ; R31.2 v3(91.82,145.92) 92.58,146.69 R23.2
  L4_SIG w0.102: v3(103.5,115.57) 103.1,115.16 101.6,115.16 96.42,109.98 83.69,109.98 83.31,109.6 83.26,109.6 v4(83.19,109.52)
  BOTTOM w0.127: v3(91.82,145.92) 91.95,145.92 95.38,142.49 95.38,141.86 97.28,139.95 97.28,131.34 97.92,130.71 97.92,118.54 101.27,115.19 103.12,115.19 v3(103.5,115.57)
A22: length 73.9
  TOP w0.102: 84.61,107.95 84.61,106.02 84.2,105.61 84.2,100.71 82.4,98.91 81.37,98.91 U9.B8
  TOP w0.127: R34.2 v3(91.82,144.65) 91.95,144.65 92.84,145.54 93.09,145.54 R32.2 ; CN11.7 v3(101.98,113.59) ; 84.61,107.95 v4(84.61,108.48)
  L4_SIG w0.102: v3(101.98,113.59) 96.88,108.48 v4(84.61,108.48)
  BOTTOM w0.127: v3(91.82,144.65) 91.95,144.65 94.49,142.11 94.49,141.48 96.52,139.45 96.52,132.08 95.25,130.81 95.25,119.2 100.86,113.59 v3(101.98,113.59)
A23: length 74.2
  TOP w0.102: v4(84.66,104.85) 84.66,100.79 82.47,98.6 80.68,98.6 U9.C8
  TOP w0.127: R39.2 90.93,139.83 v3(92.06,139.83) 92.3,139.83 92.49,139.64 92.52,139.64 92.84,139.32 R40.2 ; CN11.16 v3(103.38,108.51)
  L4_SIG w0.102: v3(103.38,108.51) 102.9,108.99 101.63,108.99 97.92,105.28 85.09,105.28 v4(84.66,104.85)
  BOTTOM w0.127: v3(92.06,139.83) 92.16,139.72 92.44,139.72 93.22,138.94 93.22,133.1 92.58,132.46 92.58,117.02 101.7,107.9 102.77,107.9 v3(103.38,108.51)
AIN_1: length 3.8
  TOP w0.127: R187.2 R186.2 37.85,28.03 37.44,28.44 U21.10
BOOT0: length 79
  TOP w0.127: v1(52.4,152.96) 52.32,153.03 R4.1 ; U4.E6 v5(81.21,139.29)
  L4_SIG w0.102: v1(52.4,152.96) 54.36,151 69.47,151 73.48,146.99 75.9,146.99 76.81,146.08 76.81,143.79 77.55,143.05 78.23,143.05 78.89,142.39 78.89,140.31 79.25,139.95 79.25,139.94 79.46,139.73 79.47,139.73 79.56,139.64 79.76,139.64 79.97,139.43 79.97,139.24 80.05,139.15 80.05,139.14 80.26,138.93 80.27,138.93 80.31,138.89 80.87,138.89 81.21,139.22 v5(81.21,139.29) 81.21,139.52 80.77,139.95 80.77,140.95 81.06,141.24 82.11,141.24 82.45,141.59 82.45,141.83 82.66,142.04 82.91,142.04 83.27,142.41 83.27,143.32 84.1,144.15 84.1,145.34 85.84,147.08 90.44,147.08 91.44,148.08 92.84,148.08 94.49,149.73 100.58,149.73 JP1.2
CAMERA_CLK: length 8.9
  TOP w0.203: CN4.20 v1(150.57,147.69) ; X3.3 145.62,147.69 v1(147.93,147.69)
  BOTTOM w0.203: v1(150.57,147.69) v1(147.93,147.69)
CUR_SEL: length 25.6
  TOP w0.127: R150.1 41.66,58.06 41.66,35.81 41.25,35.41 U21.22
D0: length 140.6
  TOP w0.102: U9.E3 77.3,104.98 71.96,104.98 71.88,104.9 ; v5(68.29,75.47) 67.92,75.85 U14.B6 ; v5(85.06,75.94) U13.R8
  TOP w0.127: v3(70.87,94.87) 70.36,95.38 70.36,103.38 71.88,104.9 ; R72.2 v1(76.45,121.28) ; v3(53.47,92.58) 52.78,93.27 CN10.39
  L4_SIG w0.102: v5(68.29,75.47) 68.29,75.49 68.42,75.62 69.04,75.62 69.47,75.18 75.72,75.18 76.05,74.85 v1(76.33,74.85) 76.38,74.85 76.61,75.08 81.15,75.08 81.61,75.54 84.66,75.54 v5(85.06,75.94) ; v3(53.47,92.58) 54.51,92.58 54.86,92.94 55.09,92.94 55.19,93.04 55.19,93.34 55.3,93.45 55.5,93.45 55.6,93.34 55.6,93.04 55.7,92.94 55.91,92.94 56.01,93.04 56.01,93.34 56.11,93.45 56.31,93.45 56.41,93.34 56.41,93.04 56.52,92.94 56.72,92.94 56.82,93.04 56.82,93.34 56.92,93.45 57.12,93.45 57.23,93.34 57.23,93.04 57.33,92.94 57.53,92.94 57.63,93.04 57.63,93.34 57.73,93.45 57.94,93.45 58.04,93.34 58.04,93.04 58.14,92.94 58.34,92.94 58.45,93.04 58.45,93.34 58.55,93.45 58.75,93.45 58.85,93.34 58.85,93.04 58.95,92.94 59.16,92.94 59.26,93.04 59.26,93.34 59.36,93.45 59.56,93.45 59.66,93.34 59.66,93.04 59.77,92.94 59.97,92.94 60.07,93.04 60.07,93.34 60.17,93.45 60.38,93.45 60.48,93.34 60.48,93.04 60.58,92.94 60.78,92.94 60.88,93.04 60.88,93.34 60.99,93.45 61.19,93.45 61.29,93.34 61.29,93.04 61.39,92.94 61.59,92.94 61.7,93.04 61.7,93.34 61.8,93.45 62,93.45 62.1,93.34 62.1,93.04 62.2,92.94 62.41,92.94 62.51,93.04 62.51,93.34 62.61,93.45 62.81,93.45 62.92,93.34 62.92,93.04 63.02,92.94 63.22,92.94 63.32,93.04 63.32,93.34 63.42,93.45 63.63,93.45 63.73,93.34 63.73,93.04 63.83,92.94 64.03,92.94 64.14,93.04 64.14,93.34 64.24,93.45 64.44,93.45 64.54,93.34 64.54,93.04 64.64,92.94 64.85,92.94 64.95,93.04 64.95,93.34 65.05,93.45 65.25,93.45 65.35,93.34 65.35,93.04 65.46,92.94 65.66,92.94 65.76,93.04 65.76,93.34 65.86,93.45 66.07,93.45 66.17,93.34 66.17,93.04 66.27,92.94 66.47,92.94 66.57,93.04 66.57,93.34 66.67,93.45 66.88,93.45 66.98,93.34 66.98,93.04 67.08,92.94 67.28,92.94 67.39,93.04 67.39,93.34 67.49,93.45 67.69,93.45 67.79,93.34 67.79,93.04 67.89,92.94 68.1,92.94 68.2,93.04 68.2,93.34 68.3,93.45 68.5,93.45 68.61,93.34 68.61,93.04 68.71,92.94 68.91,92.94 69.01,93.04 69.01,93.34 69.11,93.45 69.32,93.45 69.42,93.34 69.42,93.04 69.52,92.94 69.72,92.94 69.82,93.04 69.82,93.34 69.93,93.45 70.13,93.45 70.23,93.34 70.23,93.04 70.33,92.94 70.59,92.94 70.87,93.22 v3(70.87,94.87)
  BOTTOM w0.127: v3(53.47,92.58) 54.36,92.58 56.39,94.61 56.9,94.61 76.45,114.17 v1(76.45,121.28) ; v3(70.87,94.87) 70.87,91.54 70.99,91.41 75.25,91.41 75.37,91.29 75.37,81.64 75.25,81.51 75.18,81.51 75.06,81.39 75.06,81.13 75.18,81.01 75.25,81.01 75.37,80.88 75.37,80.63 75.25,80.5 75.18,80.5 75.06,80.37 75.06,80.12 75.18,79.99 75.25,79.99 75.37,79.86 75.37,79.61 75.25,79.48 75.18,79.48 75.06,79.36 75.06,79.1 75.18,78.97 75.25,78.97 75.37,78.85 75.37,78.59 75.25,78.47 75.18,78.47 75.06,78.34 75.06,78.09 75.18,77.96 75.25,77.96 75.37,77.83 75.37,77.58 75.25,77.45 75.18,77.45 75.06,77.32 75.06,77.07 75.18,76.94 75.25,76.94 75.37,76.82 75.37,76.56 75.25,76.43 75.18,76.43 75.06,76.31 75.06,76.05 75.18,75.93 75.25,75.93 75.37,75.8 75.37,75.55 75.25,75.42 75.18,75.42 75.06,75.29 75.06,75.04 75.18,74.91 76.27,74.91 v1(76.33,74.85)
D1: length 141.8
  TOP w0.102: 71.88,103.12 73.13,104.37 U9.H3 ; v5(86.66,76.74) U13.N7 ; U14.C5 v5(67.54,76.73)
  TOP w0.127: v3(54.91,94.95) 55.35,94.95 55.75,94.54 CN10.38 ; 71.88,103.12 71.5,102.74 71.5,101.27 70.87,100.63 v3(70.87,95.76) ; R60.2 v3(76.45,124.84)
  L4_SIG w0.102: v5(86.66,76.74) 86.26,76.34 84.85,76.34 84.35,75.84 81.46,75.84 81,75.39 76.5,75.39 v1(76.33,75.56) 75.28,75.56 75.13,75.72 74.87,75.72 74.72,75.56 74.47,75.56 74.31,75.72 74.06,75.72 73.91,75.56 73.65,75.56 73.5,75.72 73.25,75.72 73.09,75.56 72.84,75.56 72.69,75.72 72.43,75.72 72.28,75.56 72.03,75.56 71.88,75.72 71.62,75.72 71.47,75.56 70.87,75.56 70.74,75.69 70.74,76.09 70.61,76.21 70.36,76.21 70.23,76.09 70.23,75.79 70.1,75.67 69.82,75.67 69.7,75.79 69.7,76.33 69.29,76.73 68.35,76.73 68.22,76.61 68.22,76.38 68.1,76.25 67.92,76.25 67.79,76.38 67.79,76.61 67.67,76.73 v5(67.54,76.73) ; v3(54.91,94.95) 55.14,94.95 55.27,94.82 55.27,93.9 55.4,93.78 55.63,93.78 55.73,93.88 55.73,94.95 55.85,95.07 56.02,95.07 56.14,94.95 56.14,93.88 56.24,93.78 56.44,93.78 56.55,93.88 56.55,95 56.66,95.12 56.83,95.12 56.95,95 56.95,93.88 57.05,93.78 70.26,93.78 70.38,93.9 70.38,95.63 70.51,95.76 v3(70.87,95.76)
  BOTTOM w0.127: v3(54.91,94.95) 54.97,95 56.63,95 75.95,114.31 75.95,124.27 76.45,124.78 v3(76.45,124.84) ; v1(76.33,75.56) 75.95,75.56 75.76,75.76 75.76,91.67 75.63,91.8 75.5,91.8 75.37,91.92 75.37,92.08 75.25,92.2 74.99,92.2 74.87,92.08 74.87,91.92 74.74,91.8 74.49,91.8 74.36,91.92 74.36,93.12 74.23,93.24 73.98,93.24 73.85,93.12 73.85,91.92 73.72,91.8 73.47,91.8 73.34,91.92 73.34,94.13 73.22,94.26 72.96,94.26 72.83,94.13 72.83,91.92 72.71,91.8 72.45,91.8 72.33,91.92 72.33,95.15 72.2,95.28 71.95,95.28 71.82,95.15 71.82,91.92 71.69,91.8 71.4,91.8 71.27,91.92 71.27,94.49 71.37,94.59 71.37,95.99 71.25,96.11 70.99,96.11 70.87,95.99 v3(70.87,95.76)
D2: length 129
  TOP w0.102: U9.E4 v4(77.41,103.87) ; v5(67.54,75.47) 67.16,75.85 U14.C6 ; v5(85.06,75.14) U13.R9
  TOP w0.127: CN11.31 v3(101.98,98.35)
  L4_SIG w0.102: v3(101.98,98.35) 101.9,98.35 100.86,99.39 86.92,99.39 86.79,99.52 86.79,101.47 86.66,101.6 86.21,101.6 86.11,101.5 86.11,99.52 86.01,99.42 85.8,99.42 85.7,99.52 85.7,101.5 85.6,101.6 85.4,101.6 85.3,101.5 85.3,99.52 85.19,99.42 84.99,99.42 84.89,99.52 84.89,101.5 84.79,101.6 82.3,101.6 81.84,101.14 79.76,101.14 77.41,103.49 v4(77.41,103.87) ; v5(85.06,75.14) 85.06,74.55 84.93,74.42 84.63,74.42 84.51,74.55 84.51,74.96 84.4,75.06 84.2,75.06 84.1,74.96 84.1,74.52 84,74.42 83.79,74.42 83.69,74.52 83.69,74.96 83.59,75.06 83.39,75.06 83.29,74.96 83.29,74.52 83.19,74.42 82.98,74.42 82.88,74.52 82.88,74.96 82.76,75.08 82.59,75.08 82.47,74.96 82.47,74.52 82.37,74.42 82.17,74.42 82.07,74.52 82.07,75.01 81.95,75.13 81.78,75.13 81.66,75.01 81.66,74.52 81.56,74.42 v1(78.87,74.42) 75.39,74.42 75.01,74.8 68.21,74.8 v5(67.54,75.47)
  BOTTOM w0.127: v3(101.98,98.35) 101.96,98.35 87.6,112.7 87.6,121.67 86.23,123.04 R267.2 ; v1(78.87,74.42) 78.87,75.82 77.72,76.96 77.72,79.98 78.99,81.25 78.99,93.45 77.98,94.46 77.98,98.36 77.83,98.51 77.83,100.78 78.36,101.31 78.36,102.87 77.41,103.82 v4(77.41,103.87)
D3: length 130.7
  TOP w0.102: U14.D5 v5(66.79,76.73) ; v4(72.64,101.35) 73.28,101.98 73.28,103 73.67,103.39 74.89,103.39 U9.H4 ; v5(86.66,75.94) U13.N8
  TOP w0.127: CN11.32 v3(103.5,98.35)
  L4_SIG w0.102: v3(103.5,98.35) 103.05,98.35 102.57,97.87 101.63,97.87 100.48,99.01 84.05,99.01 82.47,100.58 79.38,100.58 78.73,101.23 72.76,101.23 v4(72.64,101.35) ; v5(86.66,75.94) 86.48,75.94 86.11,75.56 85.72,75.56 85.47,75.31 85.47,74.52 85.06,74.12 79.2,74.12 78.99,73.91 74.93,73.91 v1(74.68,74.17) 74.15,74.17 74.05,74.27 74.05,74.37 73.95,74.47 73.74,74.47 73.64,74.37 73.64,74.27 73.54,74.17 73.34,74.17 73.23,74.27 73.23,74.37 73.13,74.47 72.93,74.47 72.83,74.37 72.83,74.27 72.73,74.17 72.52,74.17 72.42,74.27 72.42,74.37 72.32,74.47 72.12,74.47 72.01,74.37 72.01,74.27 71.91,74.17 71.71,74.17 71.61,74.27 71.61,74.37 71.51,74.47 71.3,74.47 71.2,74.37 71.2,74.27 71.1,74.17 70.9,74.17 70.8,74.27 70.8,74.37 70.69,74.47 70.49,74.47 70.39,74.37 70.39,74.27 70.29,74.17 70.08,74.17 69.98,74.27 69.98,74.37 69.88,74.47 69.68,74.47 69.58,74.37 69.58,74.27 69.47,74.17 69.27,74.17 69.17,74.27 69.17,74.37 69.07,74.47 68.87,74.47 68.76,74.37 68.76,74.27 68.66,74.17 68.3,74.17 67.18,75.29 67.18,76.34 v5(66.79,76.73)
  BOTTOM w0.127: v4(72.64,101.35) 72.11,100.81 72.11,98.96 69.6,96.44 69.6,88.65 69.93,88.32 72.31,88.32 73.98,86.65 73.98,83.13 74.3,82.81 74.3,81.99 74.68,81.61 v1(74.68,74.17) ; v3(103.5,98.35) 102.95,97.79 101.84,97.79 101.49,98.14 101.49,98.26 87.2,112.55 87.2,121.13 86.54,121.79 R276.2
D4: length 120.7
  TOP w0.102: U9.H5 74.91,102.38 v4(74.42,102.87) ; v5(85.86,75.14) U13.P9 ; U14.E5 v5(65.29,76.73)
  TOP w0.127: v1(64.52,121.28) R63.2 ; CN10.11 v3(53.39,111.05)
  L4_SIG w0.102: v5(65.29,76.73) 65.76,76.26 65.78,76.26 68.5,73.53 77.48,73.53 v1(77.53,73.48) 77.55,73.48 77.6,73.53 79.04,73.53 79.32,73.81 79.59,73.81 79.69,73.71 79.69,73.36 79.79,73.25 79.99,73.25 80.09,73.36 80.09,73.71 80.2,73.81 80.4,73.81 80.5,73.71 80.5,73.36 80.6,73.25 80.81,73.25 80.91,73.36 80.91,73.71 81.01,73.81 81.21,73.81 81.31,73.71 81.31,73.36 81.41,73.25 81.62,73.25 81.72,73.36 81.72,73.71 81.82,73.81 82.02,73.81 82.13,73.71 82.13,73.36 82.23,73.25 82.43,73.25 82.53,73.36 82.53,73.71 82.63,73.81 85.19,73.81 85.86,74.48 v5(85.86,75.14) ; v3(53.39,111.05) 54.13,110.31 55.22,110.31 55.32,110.41 55.32,110.79 55.42,110.9 55.63,110.9 55.73,110.79 55.73,110.41 55.83,110.31 56.03,110.31 56.13,110.41 56.13,110.79 56.24,110.9 56.44,110.9 56.54,110.79 56.54,110.41 56.64,110.31 56.84,110.31 56.95,110.41 56.95,110.79 57.05,110.9 57.25,110.9 57.35,110.79 57.35,110.41 57.45,110.31 57.66,110.31 57.76,110.41 57.76,110.79 57.86,110.9 58.06,110.9 58.17,110.79 58.17,110.41 58.27,110.31 58.47,110.31 58.57,110.41 58.57,110.79 58.67,110.9 58.88,110.9 58.98,110.79 58.98,110.41 59.08,110.31 59.28,110.31 59.38,110.41 59.38,110.79 59.49,110.9 59.69,110.9 59.79,110.79 59.79,110.41 59.89,110.31 60.1,110.31 60.2,110.41 60.2,110.79 60.3,110.9 60.5,110.9 60.6,110.79 60.6,110.41 60.71,110.31 60.91,110.31 61.01,110.41 61.01,110.79 61.11,110.9 61.32,110.9 61.42,110.79 61.42,110.41 61.52,110.31 61.72,110.31 61.82,110.41 61.82,110.79 61.92,110.9 62.13,110.9 62.23,110.79 62.23,110.41 62.33,110.31 62.53,110.31 62.64,110.41 62.64,110.79 62.74,110.9 62.94,110.9 63.04,110.79 63.04,110.41 63.14,110.31 63.35,110.31 63.45,110.41 63.45,110.79 63.55,110.9 63.75,110.9 63.86,110.79 63.86,110.41 63.96,110.31 64.16,110.31 64.26,110.41 64.26,110.79 64.36,110.9 64.57,110.9 64.67,110.79 64.67,110.41 64.77,110.31 64.97,110.31 65.07,110.41 65.07,110.68 65.19,110.79 65.36,110.79 65.48,110.68 65.48,110.41 65.58,110.31 65.84,110.31 70.84,105.31 70.84,105.17 70.24,104.58 70.24,104.43 70.39,104.29 70.53,104.29 71.12,104.88 71.27,104.88 71.41,104.74 71.41,104.59 70.82,104 70.82,103.86 70.96,103.71 71.11,103.71 71.7,104.31 71.84,104.31 73.66,102.49 74.04,102.49 v4(74.42,102.87)
  BOTTOM w0.127: v4(74.42,102.87) 73.89,102.34 73.89,98.2 72.54,96.85 72.54,96.04 76.52,92.06 76.52,76.55 77.22,75.85 77.22,73.8 v1(77.53,73.48) ; v1(64.52,121.28) 64.52,118.72 57.43,111.63 53.98,111.63 v3(53.39,111.05)
D5: length 128.8
  TOP w0.102: U9.E5 v4(77.41,102.87) ; U14.F5 v5(64.54,76.73) ; v5(87.46,75.94) U13.M8
  TOP w0.127: R53.2 v1(66.55,124.59) ; CN10.14 v3(54.81,109.78)
  L4_SIG w0.102: v5(64.54,76.73) 64.15,76.34 64.15,75.83 67.34,72.64 v1(78.49,72.64) 83.19,72.64 83.29,72.75 83.29,73.08 83.39,73.18 83.59,73.18 83.69,73.08 83.69,72.75 83.79,72.64 84,72.64 84.1,72.75 84.1,73.08 84.2,73.18 84.4,73.18 84.51,73.08 84.51,72.75 84.61,72.64 84.81,72.64 84.91,72.75 84.91,73.08 85.01,73.18 85.22,73.18 85.32,73.08 85.32,72.75 85.42,72.64 85.74,72.64 85.84,72.75 85.84,73.58 85.96,73.71 87.15,73.71 87.27,73.84 87.27,74.02 87.15,74.14 86.66,74.14 86.54,74.27 86.54,74.4 86.66,74.52 86.98,74.52 87.1,74.65 87.1,75.42 87.46,75.78 v5(87.46,75.94) ; v3(54.81,109.78) 64.41,109.78 64.65,109.55 64.79,109.55 65.26,110.01 65.4,110.01 65.55,109.87 65.55,109.72 65.08,109.26 65.08,109.11 65.22,108.97 65.37,108.97 65.83,109.44 65.98,109.44 66.12,109.29 66.12,109.15 65.65,108.68 65.65,108.54 65.8,108.4 65.94,108.4 66.41,108.86 66.55,108.86 66.7,108.72 66.7,108.57 66.23,108.11 66.23,107.96 66.37,107.82 66.52,107.82 66.98,108.29 67.13,108.29 67.27,108.14 67.27,108 66.8,107.53 66.8,107.39 66.95,107.24 67.09,107.24 67.56,107.71 67.7,107.71 67.85,107.57 67.85,107.42 67.38,106.96 67.38,106.81 67.52,106.67 67.67,106.67 68.13,107.14 68.28,107.14 68.42,106.99 68.42,106.85 67.95,106.38 67.95,106.24 68.1,106.09 68.24,106.09 68.71,106.56 68.85,106.56 69,106.42 69,106.27 68.53,105.81 68.53,105.66 68.67,105.52 68.82,105.52 69.28,105.99 69.43,105.99 69.57,105.84 69.57,105.7 69.1,105.23 69.1,105.09 71.07,103.12 72.39,103.12 73.29,102.22 75.85,102.22 76.5,102.87 v4(77.41,102.87)
  BOTTOM w0.127: v3(54.81,109.78) 57.84,109.78 66.04,117.98 66.04,123.83 66.55,124.33 v1(66.55,124.59) ; v1(78.49,72.64) 78.49,73.91 78.11,74.3 78.11,76.04 77.34,76.8 77.34,80.14 78.61,81.41 78.61,93.27 77.6,94.28 77.6,98.33 76.96,98.96 76.96,100.85 77.82,101.7 77.82,102.46 v4(77.41,102.87)
D6: length 124.8
  TOP w0.102: U9.H6 74.91,101.37 73.81,102.46 v4(73.81,102.89) ; U14.F6 v5(64.54,75.98) ; v5(87.46,76.74) U13.M7
  TOP w0.127: CN10.12 v3(54.79,111.05) ; R52.2 v1(65.53,124.59)
  L4_SIG w0.102: v4(73.81,102.89) 65.48,111.23 54.97,111.23 v3(54.79,111.05) ; v5(64.54,75.98) 64.54,75.97 67.44,73.08 v1(76.83,73.08) 76.96,72.95 77.77,72.95 77.98,73.15 78.69,73.15 78.89,72.95 82.75,72.95 82.88,73.08 82.88,73.36 83.01,73.48 85.29,73.48 86.23,74.42 86.23,75.22 86.51,75.5 86.72,75.5 87.01,75.79 87.01,76.3 v5(87.46,76.74)
  BOTTOM w0.127: v1(76.83,73.08) 76.76,73 75.2,73 75.08,72.87 75.08,72.39 74.95,72.26 74.7,72.26 74.57,72.39 74.57,72.87 74.44,73 74.19,73 74.06,72.87 74.06,72.42 73.93,72.29 72.85,72.29 72.72,72.42 72.72,74.12 72.85,74.24 73.03,74.24 73.15,74.12 73.15,72.87 73.28,72.75 73.54,72.75 73.66,72.87 73.66,74.12 73.79,74.24 74.05,74.24 74.17,74.12 74.17,73.56 74.3,73.43 76.45,73.43 76.58,73.56 76.58,73.84 76.45,73.96 75.36,73.96 75.23,74.09 75.23,74.27 75.36,74.4 76.71,74.4 76.83,74.52 76.83,75.69 76.14,76.39 76.14,91.88 72.14,95.89 72.14,97 73.56,98.42 73.56,102.64 v4(73.81,102.89) ; v3(54.79,111.05) 57.64,111.05 65.01,118.42 65.01,121.4 65.02,121.41 65.02,123.95 65.53,124.46 v1(65.53,124.59)
D7: length 124.4
  TOP w0.102: U14.G6 v5(63.79,75.98) ; U9.E6 v4(77.41,101.87) ; v5(88.26,75.94) U13.L8
  TOP w0.127: CN10.13 v3(53.39,109.78) ; R64.2 v1(65.53,121.28)
  L4_SIG w0.102: v5(88.26,75.94) 87.88,75.56 87.88,73.99 86.99,73.1 86.85,73.1 86.55,73.4 86.38,73.4 86.26,73.28 86.26,73.11 86.56,72.81 86.56,72.67 86.08,72.19 77.5,72.19 v1(77.47,72.21) 67.34,72.21 63.79,75.76 v5(63.79,75.98) ; v4(77.41,101.87) 76.98,102.3 76.21,102.3 75.77,101.85 73.15,101.85 72.24,102.77 70.97,102.77 64.52,109.22 53.95,109.22 v3(53.39,109.78)
  BOTTOM w0.127: v3(53.39,109.78) 54.1,110.49 57.78,110.49 65.53,118.24 v1(65.53,121.28) ; v1(77.47,72.21) 77.47,71.88 77.34,71.75 77.09,71.75 76.96,71.88 76.96,72.39 76.83,72.52 76.65,72.52 76.52,72.39 76.52,71.88 76.4,71.75 76.14,71.75 76.02,71.88 76.02,72.39 75.89,72.52 75.64,72.52 75.51,72.39 75.51,71.88 75.38,71.75 74.12,71.75 73.99,71.63 73.99,71.22 74.12,71.09 77.85,71.09 77.98,71.22 77.98,73.79 77.6,74.17 77.6,76.01 76.9,76.71 76.9,80.23 78.23,81.56 78.23,93.11 77.22,94.13 77.22,98.17 76.58,98.81 76.58,101.05 77.34,101.81 77.35,101.81 v4(77.41,101.87)
D8: length 133.4
  TOP w0.102: U9.F3 76.51,103.97 73.23,103.97 72.01,102.74 v4(72.01,102.36) ; U14.B1 67.92,80.62 v5(67.94,80.64) ; v5(88.26,81.54) U13.L2
  TOP w0.127: CN10.16 v3(54.86,108.51) ; R54.2 v1(67.56,124.59)
  L4_SIG w0.102: v3(54.86,108.51) 64.8,108.51 70.94,102.36 v4(72.01,102.36) ; v5(88.26,81.54) 87.88,81.16 87.88,80.44 87.62,80.18 84.66,80.18 84.15,80.7 82.68,80.7 82.3,80.31 74.35,80.31 v1(74.23,80.44) 74.15,80.37 70.33,80.37 69.65,79.68 67.45,79.68 67.35,79.58 67.35,79.44 67.24,79.34 67.04,79.34 66.94,79.44 66.94,79.58 66.84,79.68 66.64,79.68 66.53,79.58 66.53,79.44 66.43,79.34 66.23,79.34 66.13,79.44 66.13,79.58 66,79.71 65.83,79.71 65.71,79.58 65.71,79.32 65.58,79.2 65.38,79.2 65.25,79.32 65.25,79.86 65.38,79.98 67.44,79.98 67.56,80.11 67.56,80.52 67.69,80.64 v5(67.94,80.64)
  BOTTOM w0.127: v3(54.86,108.51) 57.84,108.51 67.06,117.73 67.06,124.08 v1(67.56,124.59) ; v4(72.01,102.36) 72.01,102.11 68.83,98.93 68.83,86.69 72.21,83.31 72.21,82.45 72.34,82.32 73.76,82.32 73.89,82.19 73.89,81.94 73.76,81.81 72.34,81.81 72.21,81.69 72.21,81.38 72.34,81.25 73.61,81.25 73.74,81.13 73.74,80.35 73.61,80.23 72.87,80.23 72.75,80.1 72.75,79.84 72.87,79.72 73.61,79.72 73.74,79.59 73.74,79.34 73.61,79.21 72.87,79.21 72.75,79.08 72.75,78.83 72.87,78.7 73.61,78.7 73.74,78.57 73.74,78.32 73.61,78.19 72.87,78.19 72.75,78.07 72.75,77.81 72.87,77.69 73.61,77.69 73.74,77.56 73.74,77.3 73.61,77.18 72.87,77.18 72.75,77.05 72.75,76.8 72.87,76.67 73.61,76.67 73.74,76.54 73.74,76.35 73.61,76.23 72.95,76.23 72.82,76.1 72.82,75.9 72.95,75.77 73.63,75.77 73.76,75.64 73.76,75.41 73.63,75.29 73,75.29 72.87,75.16 72.87,74.83 73,74.7 74.1,74.7 74.23,74.83 v1(74.23,80.44)
D9: length 131.4
  TOP w0.102: U14.C1 67.19,80.13 v5(67.19,80.64) ; 71.88,104.01 72.64,104.78 75.5,104.78 U9.G3 ; v5(87.46,80.74) U13.M3
  TOP w0.127: v1(71.03,101.77) 71.07,101.8 71.07,103.2 71.88,104.01 ; CN10.15 v3(53.42,108.51) ; R65.2 v1(66.55,121.28)
  L4_SIG w0.102: v1(71.03,101.77) 64.97,107.82 54.61,107.82 53.92,108.51 v3(53.42,108.51) ; v5(87.46,80.74) 87.1,80.38 84.91,80.38 84.3,81 82.52,81 82.14,80.62 74.75,80.62 74.45,80.92 73.84,80.92 73.71,80.8 v1(72.75,80.8) 71.78,80.8 71.55,81.03 71.37,81.03 71.25,80.9 71.25,80.77 71.12,80.64 70.94,80.64 70.82,80.77 70.82,80.9 70.69,81.03 70.48,81.03 70.38,80.92 70.38,80.77 70.28,80.67 70.08,80.67 69.98,80.77 69.98,80.92 69.87,81.03 69.67,81.03 69.57,80.92 69.57,80.05 69.45,79.93 67.95,79.93 67.84,80.04 67.84,80.19 67.95,80.29 69.01,80.29 69.14,80.42 69.14,80.9 69.01,81.03 65.51,81.03 65.28,80.8 65.28,80.39 65.41,80.26 67.01,80.26 67.19,80.45 v5(67.19,80.64)
  BOTTOM w0.127: v3(53.42,108.51) 54,109.09 57.78,109.09 66.55,117.86 v1(66.55,121.28) ; v1(72.75,80.8) 72.34,80.39 72.34,73.1 72.21,72.97 70.36,72.97 70.23,73.1 70.23,73.36 70.36,73.48 71.65,73.48 71.78,73.61 71.78,73.81 71.65,73.94 70.36,73.94 70.23,74.07 70.23,74.32 70.36,74.45 71.68,74.45 71.81,74.57 71.81,74.83 71.68,74.96 70.38,74.96 70.26,75.08 70.26,75.34 70.38,75.46 71.7,75.46 71.83,75.59 71.83,83.13 68.45,86.51 68.45,99.21 71.01,101.77 v1(71.03,101.77)
D10: length 132.2
  TOP w0.102: v4(72.52,100.6) 72.91,100.99 75.08,100.99 75.33,101.23 75.33,102.79 75.53,102.99 76.53,102.99 U9.F4 ; 66.29,82.8 66.29,81.66 66.8,81.15 66.8,79.72 U14.C2 ; v5(87.46,81.54) U13.M2
  TOP w0.127: CN10.19 v3(53.42,105.97) ; v5(66.29,83.82) 66.29,82.8 ; R67.2 v1(68.58,121.28)
  L4_SIG w0.102: v5(87.46,81.54) 86.45,82.55 86.45,82.74 85.75,83.44 74.55,83.44 v1(74.42,83.31) 66.42,83.31 66.29,83.44 v5(66.29,83.82) ; v4(72.52,100.6) 72,101.12 71.53,101.12 71.37,100.97 70.64,100.97 70.12,101.49 69.97,101.49 69.52,101.03 69.38,101.03 69.23,101.18 69.23,101.32 69.68,101.77 69.68,101.92 69.54,102.06 69.4,102.06 68.94,101.61 68.8,101.61 68.66,101.75 68.66,101.9 69.11,102.35 69.11,102.49 68.97,102.64 68.82,102.64 68.37,102.18 68.23,102.18 68.08,102.33 68.08,102.47 68.53,102.92 68.53,103.07 68.39,103.21 68.25,103.21 67.79,102.76 67.65,102.76 67.51,102.9 67.51,103.05 67.96,103.5 67.96,103.64 67.82,103.79 67.67,103.79 67.22,103.33 67.08,103.33 66.93,103.48 66.93,103.62 67.38,104.07 67.38,104.22 67.24,104.36 67.1,104.36 66.64,103.91 66.5,103.91 66.36,104.05 66.36,104.2 66.81,104.65 66.81,104.79 66.67,104.94 66.52,104.94 66.07,104.48 65.93,104.48 65.78,104.63 65.78,104.77 66.23,105.22 66.23,105.37 65.05,106.55 54,106.55 v3(53.42,105.97)
  BOTTOM w0.127: v4(72.52,100.6) 72.52,98.81 69.98,96.27 69.98,90.78 70.1,90.65 70.48,90.65 70.61,90.53 70.61,90.32 70.48,90.2 70.13,90.2 70,90.07 70,89.87 70.13,89.74 70.46,89.74 70.59,89.61 70.59,89.43 70.46,89.31 70.1,89.31 69.98,89.18 69.98,88.85 70.1,88.72 70.89,88.72 71.02,88.85 71.02,90.53 71.15,90.65 71.35,90.65 71.48,90.53 71.48,88.85 71.6,88.72 71.81,88.72 71.93,88.85 71.93,90.53 72.06,90.65 72.31,90.65 72.44,90.53 72.44,88.85 72.57,88.72 72.82,88.72 72.95,88.85 72.95,90.53 73.08,90.65 73.33,90.65 73.46,90.53 73.46,88.85 73.58,88.72 73.84,88.72 73.96,88.85 73.96,90.53 74.09,90.65 74.3,90.65 74.42,90.53 v1(74.42,83.31) ; v3(53.42,105.97) 54.13,106.68 57.91,106.68 68.58,117.35 v1(68.58,121.28)
